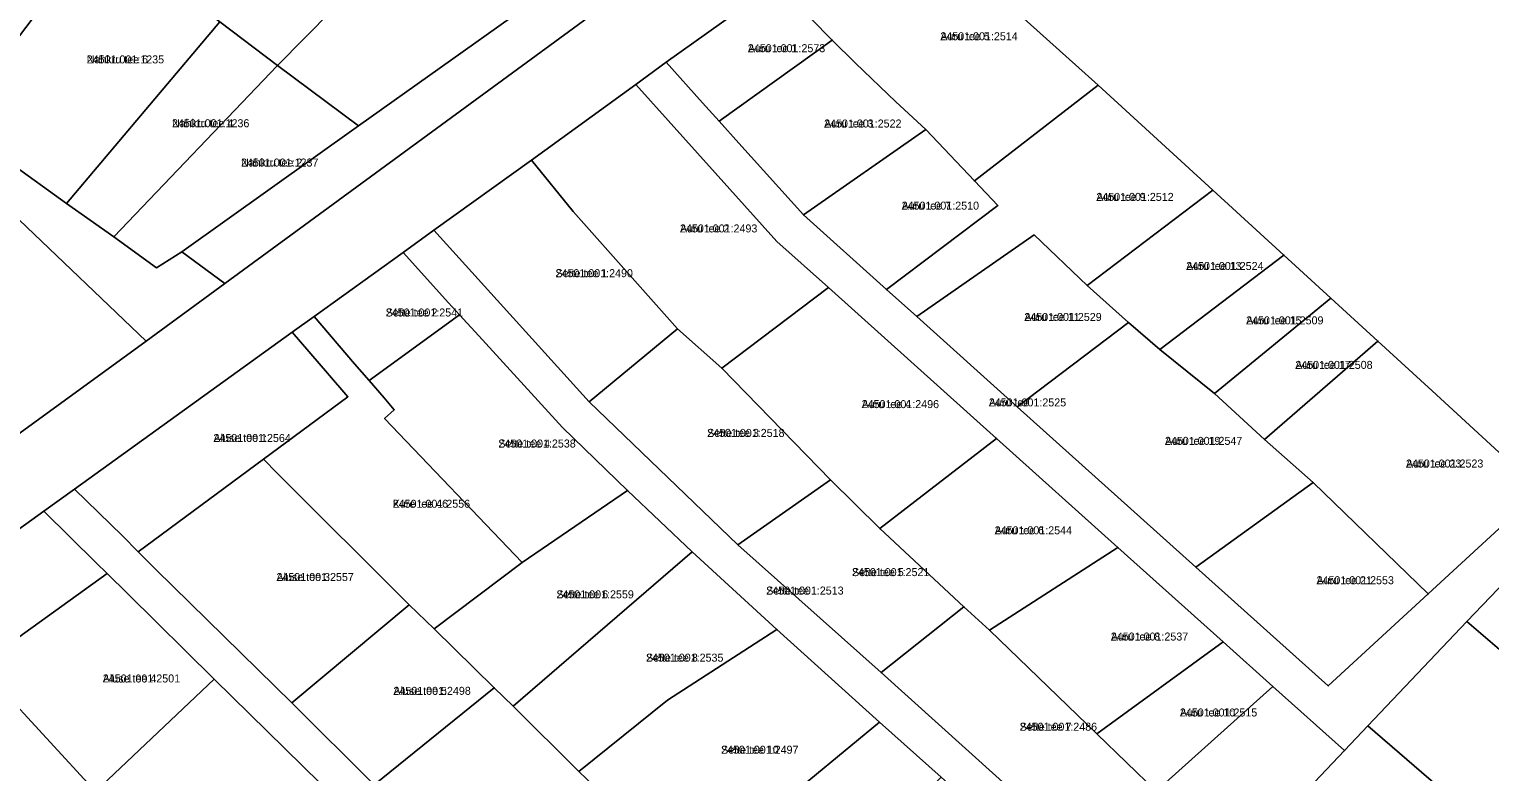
# Model space of a CAD drawing. Extents: x 551291 to 575799, y 6581704 to 6610137.
# Drawn here: x 559109.5 to 559383.3, y 6593632.5 to 6593771.7 of the extents above; entities that cross this region are included whole.
import ezdxf

# ---------------------------------------------------------------- set-up
doc = ezdxf.new("R2010")
doc.units = 0
for name, color, linetype in [('L_AADRESS', 7, 'Continuous'), ('PIIR', 7, 'Continuous'), ('TUNNUS', 7, 'Continuous')]:
    doc.layers.add(name, color=color, linetype=linetype)

msp = doc.modelspace()

# ---------------------------------------------------------------- linework, layer by layer
at = {"layer": 'PIIR'}
for points in [[(558177.52, 6592770.55), (558170.99, 6592891.67), (558187.73, 6592959.33), (558210.3, 6593010.98), (558251.88, 6593067.47), (558331.23, 6593148.23), (558500.98, 6593273.8), (558515.98, 6593265.59), (558725.44, 6593417.8), (558892.15, 6593539.14), (558974.44, 6593599.03), (559131.4, 6593713.23), (559146.17, 6593723.99), (559299.06, 6593836.09), (559444.58, 6594136.67), (559447.22, 6594142.1), (559464.89, 6594178.58), (559481.53, 6594212.94), (559484.05, 6594218.05)], [(559065.81, 6593775.35), (559080.62, 6593764.69), (559095.34, 6593754.29), (559116.5, 6593739), (559125.35, 6593732.76), (559133.35, 6593726.98), (559138.1, 6593729.93), (559146.17, 6593723.99), (559131.4, 6593713.23), (559107.63, 6593735.97), (558991.73, 6593820.06)], [(559249.66, 6593780.34), (559228.92, 6593765.5), (559223.23, 6593761.3), (559203.64, 6593747.15), (559185.32, 6593733.99), (559179.59, 6593729.84), (559162.91, 6593717.82), (559158.82, 6593714.91), (559118, 6593685.43), (559112.27, 6593681.32), (559064.17, 6593646.66), (559058.46, 6593642.47), (559036.38, 6593626.58), (558930.78, 6593550.24), (558598.95, 6593310.7)], [(559167.42, 6593627.02), (559144.16, 6593649.83), (559128.01, 6593665.84), (559124.12, 6593669.65), (559122.08, 6593671.64), (559112.27, 6593681.32), (559118, 6593685.43), (559127.01, 6593676.68), (559129.96, 6593673.7), (559133.31, 6593670.32), (559158.73, 6593645.4), (559174.15, 6593630.04)], [(559388.67, 6593526.29), (559382.69, 6593532.27), (559380.27, 6593534.92), (559373.54, 6593542.33), (559353.15, 6593565.06), (559349.3, 6593568.68), (559329.96, 6593587.8), (559319.12, 6593597.39), (559323.52, 6593602.12), (559356.05, 6593636.44), (559360.43, 6593641.06), (559395.61, 6593610.72)]]:
    msp.add_lwpolyline(points, dxfattribs=at)
for points in [[(559171.21, 6593753.59), (559201.87, 6593775.34), (559209.55, 6593780.73), (559246.25, 6593806.94), (559271.02, 6593824.58), (559293.51, 6593840.52), (559316.24, 6593887.55), (559335.18, 6593926.77), (559358.82, 6593975.74), (559369.18, 6593996.97), (559372.27, 6594003.33), (559388.13, 6594036.07), (559408, 6594077.05), (559411.94, 6594085.21), (559438.12, 6594139.38), (559444.58, 6594136.67), (559299.06, 6593836.09), (559146.17, 6593723.99), (559138.1, 6593729.93)], [(558848.05, 6593879.64), (558864.79, 6593918.03), (558860.47, 6593928.98), (558903.67, 6593906.99), (558909.72, 6593881.1), (558919.99, 6593867.54), (558991.73, 6593820.06), (559107.63, 6593735.97), (559131.4, 6593713.23), (558974.44, 6593599.03), (558967.52, 6593607.41), (558955.89, 6593623.55), (558983.88, 6593649.3), (558928.27, 6593700.28), (558901.17, 6593726.09), (558876.72, 6593752.5), (558850.2, 6593776.1), (558837.39, 6593784.85), (558822.68, 6593787.24), (558821.73, 6593800.8), (558836.41, 6593829.86), (558843.39, 6593830.35), (558853.81, 6593877.09)], [(559400.41, 6593682.53), (559398.02, 6593680.52), (559392.78, 6593685.23), (559372.46, 6593703.92), (559362.29, 6593713.22), (559353.5, 6593721.24), (559344.69, 6593729.33), (559331.38, 6593741.49), (559309.88, 6593761.17), (559271.2, 6593795.97), (559293.37, 6593811.67), (559299.35, 6593813.89), (559312.56, 6593828.02), (559358.56, 6593852.25), (559366.12, 6593842.62), (559485.21, 6593757.68), (559465.82, 6593735.48), (559464.42, 6593733.88), (559460.32, 6593730.35), (559434.91, 6593708.44), (559433.03, 6593707.03), (559426.01, 6593701.76), (559420.53, 6593697.64), (559406.41, 6593687.04)], [(559145.23, 6593773.06), (559143.09, 6593774.7), (559168.21, 6593801.51), (559181.7, 6593790.95), (559156.03, 6593764.89)], [(559249.66, 6593780.34), (559271.2, 6593795.97), (559309.88, 6593761.17), (559286.68, 6593743.26), (559277.59, 6593752.86), (559271.93, 6593758.09), (559264.37, 6593765.3), (559260.03, 6593769.65), (559256, 6593773.68)], [(559171.21, 6593753.59), (559156.03, 6593764.89), (559181.7, 6593790.95), (559201.87, 6593775.34)], [(559116.5, 6593739), (559095.34, 6593754.29), (559122.37, 6593789.82), (559131.65, 6593783.04), (559143.09, 6593774.7), (559145.23, 6593773.06)], [(559228.92, 6593765.5), (559249.66, 6593780.34), (559256, 6593773.68), (559260.03, 6593769.65), (559238.81, 6593754.43), (559235.7, 6593757.89)], [(559125.35, 6593732.76), (559116.5, 6593739), (559145.23, 6593773.06), (559156.03, 6593764.89)], [(559238.81, 6593754.43), (559260.03, 6593769.65), (559264.37, 6593765.3), (559271.93, 6593758.09), (559277.59, 6593752.86), (559254.62, 6593736.88), (559242.5, 6593750.32)], [(559133.35, 6593726.98), (559125.35, 6593732.76), (559156.03, 6593764.89), (559171.21, 6593753.59), (559138.1, 6593729.93)], [(559223.23, 6593761.3), (559228.92, 6593765.5), (559235.7, 6593757.89), (559238.81, 6593754.43), (559242.5, 6593750.32), (559254.62, 6593736.88), (559270.18, 6593722.86), (559275.86, 6593717.83), (559294.69, 6593700.86), (559328.18, 6593670.83), (559352.99, 6593648.57), (559371.73, 6593665.8), (559392.78, 6593685.23), (559398.02, 6593680.52), (559378.93, 6593660.64), (559360.43, 6593641.06), (559356.05, 6593636.44), (559342.59, 6593648.47), (559333.26, 6593656.84), (559313.57, 6593674.54), (559290.82, 6593694.98), (559259.32, 6593723.24), (559249.66, 6593731.86)], [(559211.48, 6593737.52), (559203.64, 6593747.15), (559223.23, 6593761.3), (559249.66, 6593731.86), (559259.32, 6593723.24), (559239.3, 6593708.13), (559230.99, 6593715.5)], [(559291.08, 6593738.65), (559286.68, 6593743.26), (559309.88, 6593761.17), (559331.38, 6593741.49), (559307.81, 6593723.65), (559297.88, 6593733.11), (559275.86, 6593717.83), (559270.18, 6593722.86)], [(559254.62, 6593736.88), (559277.59, 6593752.86), (559286.68, 6593743.26), (559291.08, 6593738.65), (559270.18, 6593722.86)], [(559214.48, 6593701.83), (559185.32, 6593733.99), (559203.64, 6593747.15), (559211.48, 6593737.52), (559230.99, 6593715.5)], [(559307.81, 6593723.65), (559331.38, 6593741.49), (559344.69, 6593729.33), (559321.43, 6593711.62), (559315.57, 6593716.7)], [(559179.59, 6593729.84), (559185.32, 6593733.99), (559214.48, 6593701.83), (559242.35, 6593675), (559269.17, 6593651.06), (559307.11, 6593616.9), (559323.52, 6593602.12), (559319.12, 6593597.39), (559304.66, 6593609.75), (559291.94, 6593621.11), (559280.42, 6593631.47), (559268.87, 6593641.79), (559249.64, 6593659.16), (559233.79, 6593673.7), (559221.66, 6593685.22), (559209.48, 6593697), (559193.77, 6593714.18), (559190.17, 6593718.15), (559188.12, 6593720.41)], [(559294.69, 6593700.86), (559275.86, 6593717.83), (559297.88, 6593733.11), (559307.81, 6593723.65), (559315.57, 6593716.7)], [(559170.48, 6593708.98), (559162.91, 6593717.82), (559179.59, 6593729.84), (559188.12, 6593720.41), (559190.17, 6593718.15), (559173.22, 6593705.82)], [(559321.43, 6593711.62), (559344.69, 6593729.33), (559353.5, 6593721.24), (559331.67, 6593703.38)], [(559239.3, 6593708.13), (559259.32, 6593723.24), (559290.82, 6593694.98), (559268.92, 6593678.07), (559259.67, 6593687.23)], [(559331.67, 6593703.38), (559353.5, 6593721.24), (559362.29, 6593713.22), (559341.04, 6593694.76)], [(559180.74, 6593663.74), (559155.98, 6593688.47), (559153.4, 6593691.05), (559169.23, 6593702.77), (559165.4, 6593707.23), (559158.82, 6593714.91), (559162.91, 6593717.82), (559170.48, 6593708.98), (559173.22, 6593705.82), (559176.06, 6593702.55), (559177.92, 6593700.35), (559176.11, 6593698.7), (559201.88, 6593671.71), (559185.41, 6593659.26)], [(559173.22, 6593705.82), (559190.17, 6593718.15), (559193.77, 6593714.18), (559209.48, 6593697), (559221.66, 6593685.22), (559201.88, 6593671.71), (559176.11, 6593698.7), (559177.92, 6593700.35), (559176.06, 6593702.55)], [(559127.01, 6593676.68), (559118, 6593685.43), (559158.82, 6593714.91), (559165.4, 6593707.23), (559169.23, 6593702.77), (559153.4, 6593691.05), (559129.96, 6593673.7)], [(559214.48, 6593701.83), (559230.99, 6593715.5), (559239.3, 6593708.13), (559259.67, 6593687.23), (559242.35, 6593675)], [(559294.69, 6593700.86), (559315.57, 6593716.7), (559321.43, 6593711.62), (559331.67, 6593703.38), (559341.04, 6593694.76), (559350.14, 6593686.7), (559328.18, 6593670.83)], [(559341.04, 6593694.76), (559362.29, 6593713.22), (559372.46, 6593703.92), (559392.78, 6593685.23), (559371.73, 6593665.8), (559350.14, 6593686.7)], [(559268.92, 6593678.07), (559290.82, 6593694.98), (559313.57, 6593674.54), (559289.48, 6593659), (559284.7, 6593663.42)], [(559133.31, 6593670.32), (559129.96, 6593673.7), (559153.4, 6593691.05), (559155.98, 6593688.47), (559180.74, 6593663.74), (559158.73, 6593645.4)], [(559242.35, 6593675), (559259.67, 6593687.23), (559268.92, 6593678.07), (559284.7, 6593663.42), (559269.17, 6593651.06)], [(559328.18, 6593670.83), (559350.14, 6593686.7), (559371.73, 6593665.8), (559352.99, 6593648.57)], [(559201.88, 6593671.71), (559221.66, 6593685.22), (559233.79, 6593673.7), (559200.24, 6593644.74), (559196.66, 6593648.21), (559185.41, 6593659.26)], [(559073, 6593638.03), (559064.17, 6593646.66), (559112.27, 6593681.32), (559122.08, 6593671.64), (559124.12, 6593669.65), (559100.12, 6593652.42), (559076.02, 6593635.12)], [(559403, 6593640.02), (559378.93, 6593660.64), (559398.02, 6593680.52), (559400.41, 6593682.53), (559416.41, 6593662.54), (559422.83, 6593656.13)], [(559200.24, 6593644.74), (559233.79, 6593673.7), (559249.64, 6593659.16), (559229.14, 6593645.87), (559212.54, 6593632.51)], [(559289.48, 6593659), (559313.57, 6593674.54), (559333.26, 6593656.84), (559309.62, 6593639.6)], [(559100.12, 6593652.42), (559124.12, 6593669.65), (559128.01, 6593665.84), (559144.16, 6593649.83), (559121.94, 6593628.77), (559103.5, 6593648.75)], [(559158.73, 6593645.4), (559180.74, 6593663.74), (559185.41, 6593659.26), (559196.66, 6593648.21), (559174.15, 6593630.04)], [(559269.17, 6593651.06), (559284.7, 6593663.42), (559289.48, 6593659), (559309.62, 6593639.6), (559320.74, 6593628.82), (559307.11, 6593616.9)], [(559395.61, 6593610.72), (559360.43, 6593641.06), (559378.93, 6593660.64), (559403, 6593640.02), (559416.54, 6593628.43)], [(559229.14, 6593645.87), (559249.64, 6593659.16), (559268.87, 6593641.79), (559233.47, 6593612.54), (559215.38, 6593629.77), (559212.54, 6593632.51)], [(559309.62, 6593639.6), (559333.26, 6593656.84), (559342.59, 6593648.47), (559320.74, 6593628.82)], [(559078.84, 6593632.41), (559076.02, 6593635.12), (559100.12, 6593652.42), (559103.5, 6593648.75), (559121.94, 6593628.77), (559135.44, 6593614.39), (559117.9, 6593594.47)], [(559121.94, 6593628.77), (559144.16, 6593649.83), (559167.42, 6593627.02), (559144.68, 6593606.58), (559135.44, 6593614.39)], [(559320.74, 6593628.82), (559342.59, 6593648.47), (559356.05, 6593636.44), (559323.52, 6593602.12), (559307.11, 6593616.9)], [(559174.15, 6593630.04), (559196.66, 6593648.21), (559200.24, 6593644.74), (559212.54, 6593632.51), (559215.38, 6593629.77), (559192.4, 6593612.28)], [(559233.47, 6593612.54), (559268.87, 6593641.79), (559280.42, 6593631.47), (559246.97, 6593599.05), (559238.03, 6593607.41)]]:
    msp.add_lwpolyline(points, close=True, dxfattribs=at)

# ---------------------------------------------------------------- texts
at = {"layer": 'L_AADRESS'}
for s, p in [('Auru tee 1', (559244.21, 6593767.38)), ('Auru tee 5', (559280.28, 6593769.62)), ('Nahkru tee 6', (559120.29, 6593765.28)), ('Nahkru tee 4', (559136.27, 6593753.31)), ('Auru tee 3', (559258.5, 6593753.26)), ('Nahkru tee 2', (559149.21, 6593745.94)), ('Auru tee 7', (559273.03, 6593737.86)), ('Auru tee 9', (559309.51, 6593739.5)), ('Auru tee 2', (559231.48, 6593733.59)), ('Auru tee 13', (559326.35, 6593726.55)), ('Sette tee 1', (559208.16, 6593725.2)), ('Sette tee 2', (559176.33, 6593717.83)), ('Auru tee 11', (559296.02, 6593716.99)), ('Auru tee 15', (559337.59, 6593716.35)), ('Auru tee 17', (559346.8, 6593708)), ('Auru tee 4', (559265.54, 6593700.65)), ('Auru tee', (559289.36, 6593700.97)), ('Aluse tee 1', (559144.04, 6593694.3)), ('Sette tee 3', (559236.58, 6593695.25)), ('Auru tee 19', (559322.38, 6593693.76)), ('Sette tee 4', (559197.44, 6593693.26)), ('Auru tee 23', (559367.55, 6593689.51)), ('Kure tee 46', (559177.64, 6593681.97)), ('Auru tee 6', (559290.46, 6593676.99)), ('Sette tee 5', (559263.72, 6593669.15)), ('Aluse tee 3', (559155.85, 6593668.23)), ('Auru tee 21', (559350.79, 6593667.63)), ('Sette tee 6', (559208.33, 6593664.98)), ('Sette tee', (559247.65, 6593665.69)), ('Auru tee 8', (559312.24, 6593657.07)), ('Sette tee 8', (559225.12, 6593653.11)), ('Aluse tee 4', (559123.29, 6593649.21)), ('Aluse tee 5', (559177.77, 6593646.89)), ('Auru tee 10', (559325.18, 6593642.83)), ('Sette tee 7', (559295.16, 6593640.16)), ('Sette tee 10', (559239.19, 6593635.85))]:
    msp.add_text(s, height=1.5, dxfattribs=at).set_placement(p)
at = {"layer": 'TUNNUS'}
for s, p in [('24501:001:2573', (559244.21, 6593767.38)), ('24501:001:2514', (559280.28, 6593769.62)), ('24501:001:1235', (559120.29, 6593765.28)), ('24501:001:1236', (559136.27, 6593753.31)), ('24501:001:2522', (559258.5, 6593753.26)), ('24501:001:1237', (559149.21, 6593745.94)), ('24501:001:2510', (559273.03, 6593737.86)), ('24501:001:2512', (559309.51, 6593739.5)), ('24501:001:2493', (559231.48, 6593733.59)), ('24501:001:2524', (559326.35, 6593726.55)), ('24501:001:2490', (559208.16, 6593725.2)), ('24501:001:2541', (559176.33, 6593717.83)), ('24501:001:2529', (559296.02, 6593716.99)), ('24501:001:2509', (559337.59, 6593716.35)), ('24501:001:2508', (559346.8, 6593708)), ('24501:001:2496', (559265.54, 6593700.65)), ('24501:001:2525', (559289.36, 6593700.97)), ('24501:001:2564', (559144.04, 6593694.3)), ('24501:001:2518', (559236.58, 6593695.25)), ('24501:001:2547', (559322.38, 6593693.76)), ('24501:001:2538', (559197.44, 6593693.26)), ('24501:001:2523', (559367.55, 6593689.51)), ('24501:001:2556', (559177.64, 6593681.97)), ('24501:001:2544', (559290.46, 6593676.99)), ('24501:001:2521', (559263.72, 6593669.15)), ('24501:001:2557', (559155.85, 6593668.23)), ('24501:001:2553', (559350.79, 6593667.63)), ('24501:001:2559', (559208.33, 6593664.98)), ('24501:001:2513', (559247.65, 6593665.69)), ('24501:001:2537', (559312.24, 6593657.07)), ('24501:001:2535', (559225.12, 6593653.11)), ('24501:001:2501', (559123.29, 6593649.21)), ('24501:001:2498', (559177.77, 6593646.89)), ('24501:001:2515', (559325.18, 6593642.83)), ('24501:001:2486', (559295.16, 6593640.16)), ('24501:001:2497', (559239.19, 6593635.85))]:
    msp.add_text(s, height=1.5, dxfattribs=at).set_placement(p)

doc.saveas('drawing.dxf')
